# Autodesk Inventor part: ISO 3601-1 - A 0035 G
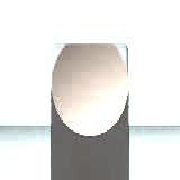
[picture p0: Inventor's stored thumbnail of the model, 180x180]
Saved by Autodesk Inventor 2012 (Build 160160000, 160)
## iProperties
Created: 2007-03
Part Number: ISO 3601-1 - A 0035 G
Material: Caoutchouc
Description: Systèmes hydrauliques - Joint torique
Document SubType Name: Modeling
Standard: ISO 3601-1
Designer: Laur
Standard Revision: Troisième édition 2002-08-01
Standards Organization: ISO
Language: fr-FR
Size Designation: A 0035 G
Categories: <MemberInstance><Categories><Category DisplayName="Pièces d'arbre" InternalName="7f7aeb1f-a693-4053-b835-cee3144e0d98" Mnemonic="SHFT"><Category DisplayName="Et
Density: 1 g/cm^3
IsCustomPart: 0
Author: Laur
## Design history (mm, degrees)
revolve "Corps" stored, may be unused: angle "d19" = 90 deg
node "Solide1"
node "Corps solides"
node "Corps surfaciques"
sketch "Esquisse1"
  geometry: L1 (-0.011, 0)-(-0.011, 0); L2 (-0.566, 1.4)-(0.566, 1.4); L3 (-0.566, 0)-(0.566, 0); L4 (-4, -2)-(6.034, -2); L5 (-6.007, 0)-(8.04, 0) reference; L6 (0, 4.64)-(0, -12.44) reference; A1 r 0.9 centre (0, 0.7) between (-0.566, 1.4) and (-0.566, 0); A2 r 0.9 centre (0, 0.7) between (0.566, 0) and (0.566, 1.4)
  constraints: 8 end point, 4 point on circle, 2 centre point, 2 horizontal alignment, 2 parallel, 1 coincident, 1 horizontal, 1 point on line, 1 other
  dimensions: "d0" = 4 diameter of L5 L4 (= NND); "d1" = 0.7 distance from line of A1.centre L2 (= -0.25 x NND + 0.25 x NDOR); "d2" = 0.9 radius of A1 (= 0.5 x QDM); "d3" = 0.7 distance from line of L3 A1.centre (= -0.25 x NND + 0.25 x NDOR); "d4" = 1.4 distance between parallel lines of L5 L2 (= -0.5 x NND + 0.5 x NDOR)
other parameters: "QDM" = 1.8 [user parameter; used in 1 equation term], "NND" = 4 [user parameter; used in 5 equation terms], "NDOR" = 6.8 [user parameter; used in 3 equation terms], "d5" = 0, "R2" = 0.2 [user parameter], "SD1" = 3.5 [user parameter], "R1" = 0.3 [user parameter], "NB2" = 3.8 [user parameter], "NB1" = 2.4 [user parameter], "NB3" = 5.2 [user parameter], "BD" = 4 (= NND) [user parameter]
